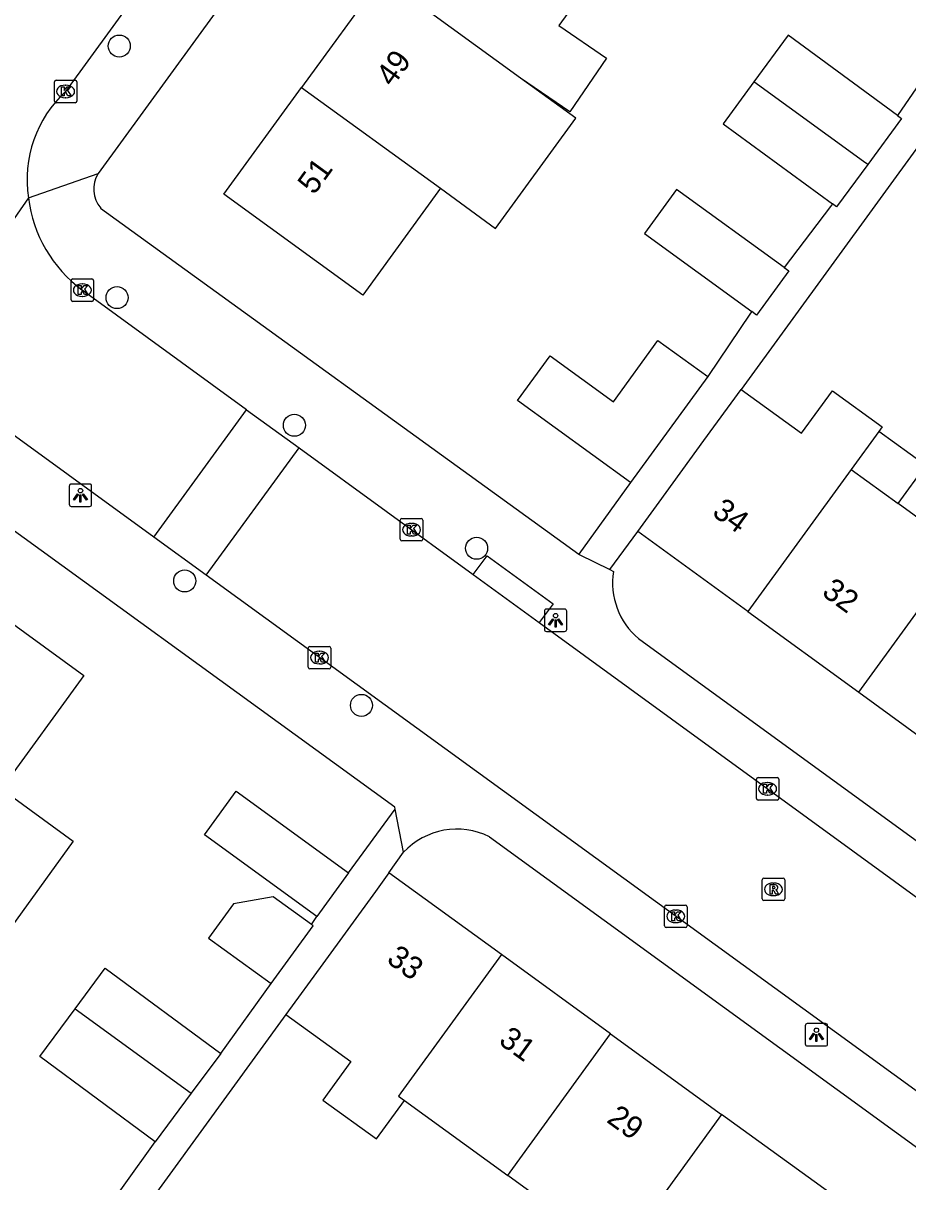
# Model space of a CAD drawing. Extents: x 159675 to 160530, y 382179 to 382901.
# Drawn here: x 160100.6 to 160139.9, y 382538.5 to 382590 of the extents above; entities that cross this region are included whole.
import ezdxf

# ---------------------------------------------------------------- set-up
doc = ezdxf.new("R2010")
doc.units = 0
for name, color, linetype in [('IMGEO_Boom', 7, 'Continuous'), ('IMGEO_Kolk', 7, 'Continuous'), ('IMGEO_Lichtpunt', 7, 'Continuous'), ('IMGEO_Pand', 7, 'Continuous'), ('IMGEO_Pand_nummerreeks', 7, 'Continuous'), ('IMGEO_Rijbaan_lokaal_open', 7, 'Continuous'), ('IMGEO_Rioolput', 7, 'Continuous'), ('IMGEO_Voetpad_open', 7, 'Continuous')]:
    doc.layers.add(name, color=color, linetype=linetype)

msp = doc.modelspace()

# ---------------------------------------------------------------- linework, layer by layer
at = {"layer": 'IMGEO_Boom'}
for centre in [(160104.827, 382589.008), (160104.727, 382577.823), (160112.605, 382572.152), (160120.699, 382566.683), (160107.733, 382565.233), (160115.586, 382559.701)]:
    msp.add_circle(centre, 0.489, dxfattribs=at)
at = {"layer": 'IMGEO_Kolk'}
for p, q in [((160101.942, 382586.562), (160101.942, 382587.414)), ((160102.017, 382587.488), (160102.869, 382587.488)), ((160102.43, 382587.268), (160102.455, 382587.268)), ((160102.943, 382587.414), (160102.943, 382586.562)), ((160102.453, 382586.708), (160102.428, 382586.708)), ((160102.869, 382586.488), (160102.017, 382586.488)), ((160102.686, 382577.731), (160102.686, 382578.583)), ((160102.761, 382578.657), (160103.613, 382578.657)), ((160103.174, 382578.437), (160103.199, 382578.437)), ((160103.687, 382578.583), (160103.687, 382577.731)), ((160103.197, 382577.877), (160103.172, 382577.877)), ((160103.613, 382577.657), (160102.761, 382577.657)), ((160117.386, 382568.009), (160118.238, 382568.009)), ((160117.311, 382567.083), (160117.311, 382567.935)), ((160117.799, 382567.789), (160117.824, 382567.789)), ((160118.312, 382567.935), (160118.312, 382567.083)), ((160118.238, 382567.009), (160117.386, 382567.009)), ((160117.822, 382567.229), (160117.797, 382567.229)), ((160113.298, 382562.324), (160114.15, 382562.324)), ((160113.223, 382561.398), (160113.223, 382562.25)), ((160113.711, 382562.104), (160113.736, 382562.104)), ((160114.224, 382562.25), (160114.224, 382561.398)), ((160114.15, 382561.324), (160113.298, 382561.324)), ((160113.734, 382561.544), (160113.709, 382561.544)), ((160133.129, 382555.567), (160133.129, 382556.419)), ((160133.204, 382556.493), (160134.056, 382556.493)), ((160133.617, 382556.273), (160133.642, 382556.273)), ((160134.13, 382556.419), (160134.13, 382555.567)), ((160133.64, 382555.713), (160133.615, 382555.713)), ((160134.056, 382555.493), (160133.204, 382555.493)), ((160129.048, 382549.897), (160129.048, 382550.749)), ((160129.123, 382550.823), (160129.975, 382550.823)), ((160129.536, 382550.603), (160129.561, 382550.603)), ((160130.049, 382550.749), (160130.049, 382549.897)), ((160129.559, 382550.043), (160129.534, 382550.043)), ((160129.975, 382549.823), (160129.123, 382549.823))]:
    msp.add_line(p, q, dxfattribs=at)
for points in [[(160101.942, 382586.562), (160101.942, 382587.414)], [(160102.017, 382587.488), (160102.869, 382587.488)], [(160102.263, 382587.188), (160102.386, 382587.188), (160102.386, 382587.037), (160102.516, 382587.188), (160102.68, 382587.188), (160102.534, 382587.037), (160102.687, 382586.788), (160102.535, 382586.788), (160102.45, 382586.952), (160102.386, 382586.885), (160102.386, 382586.788), (160102.263, 382586.788), (160102.263, 382587.188)], [(160102.943, 382587.414), (160102.943, 382586.562)], [(160102.869, 382586.488), (160102.017, 382586.488)], [(160102.686, 382577.731), (160102.686, 382578.583)], [(160102.761, 382578.657), (160103.613, 382578.657)], [(160103.007, 382578.357), (160103.13, 382578.357), (160103.13, 382578.206), (160103.26, 382578.357), (160103.424, 382578.357), (160103.278, 382578.206), (160103.431, 382577.957), (160103.279, 382577.957), (160103.194, 382578.121), (160103.13, 382578.054), (160103.13, 382577.957), (160103.007, 382577.957), (160103.007, 382578.357)], [(160103.687, 382578.583), (160103.687, 382577.731)], [(160103.613, 382577.657), (160102.761, 382577.657)], [(160117.386, 382568.009), (160118.238, 382568.009)], [(160117.311, 382567.083), (160117.311, 382567.935)], [(160117.632, 382567.709), (160117.755, 382567.709), (160117.755, 382567.558), (160117.885, 382567.709), (160118.049, 382567.709), (160117.903, 382567.558), (160118.056, 382567.309), (160117.904, 382567.309), (160117.819, 382567.473), (160117.755, 382567.406), (160117.755, 382567.309), (160117.632, 382567.309), (160117.632, 382567.709)], [(160118.312, 382567.935), (160118.312, 382567.083)], [(160118.238, 382567.009), (160117.386, 382567.009)], [(160113.298, 382562.324), (160114.15, 382562.324)], [(160113.223, 382561.398), (160113.223, 382562.25)], [(160113.544, 382562.024), (160113.667, 382562.024), (160113.667, 382561.873), (160113.797, 382562.024), (160113.961, 382562.024), (160113.815, 382561.873), (160113.968, 382561.624), (160113.816, 382561.624), (160113.731, 382561.788), (160113.667, 382561.721), (160113.667, 382561.624), (160113.544, 382561.624), (160113.544, 382562.024)], [(160114.224, 382562.25), (160114.224, 382561.398)], [(160114.15, 382561.324), (160113.298, 382561.324)], [(160133.129, 382555.567), (160133.129, 382556.419)], [(160133.204, 382556.493), (160134.056, 382556.493)], [(160133.45, 382556.193), (160133.573, 382556.193), (160133.573, 382556.042), (160133.703, 382556.193), (160133.867, 382556.193), (160133.721, 382556.042), (160133.874, 382555.793), (160133.722, 382555.793), (160133.637, 382555.957), (160133.573, 382555.89), (160133.573, 382555.793), (160133.45, 382555.793), (160133.45, 382556.193)], [(160134.13, 382556.419), (160134.13, 382555.567)], [(160134.056, 382555.493), (160133.204, 382555.493)], [(160129.048, 382549.897), (160129.048, 382550.749)], [(160129.123, 382550.823), (160129.975, 382550.823)], [(160129.369, 382550.523), (160129.492, 382550.523), (160129.492, 382550.372), (160129.622, 382550.523), (160129.786, 382550.523), (160129.64, 382550.372), (160129.793, 382550.123), (160129.641, 382550.123), (160129.556, 382550.287), (160129.492, 382550.22), (160129.492, 382550.123), (160129.369, 382550.123), (160129.369, 382550.523)], [(160130.049, 382550.749), (160130.049, 382549.897)], [(160129.975, 382549.823), (160129.123, 382549.823)]]:
    msp.add_lwpolyline(points, dxfattribs=at)
for centre, start, end in [((160102.019, 382587.412), 91.552, 178.448), ((160102.019, 382587.412), 91.552, 178.448), ((160102.867, 382587.412), 1.552, 88.448), ((160102.867, 382587.412), 1.552, 88.448), ((160102.019, 382586.564), 181.552, 268.448), ((160102.019, 382586.564), 181.552, 268.448), ((160102.867, 382586.564), 271.552, 358.448), ((160102.867, 382586.564), 271.552, 358.448), ((160102.763, 382578.581), 91.552, 178.448), ((160102.763, 382578.581), 91.552, 178.448), ((160103.611, 382578.581), 1.552, 88.448), ((160103.611, 382578.581), 1.552, 88.448), ((160102.763, 382577.733), 181.552, 268.448), ((160102.763, 382577.733), 181.552, 268.448), ((160103.611, 382577.733), 271.552, 358.448), ((160103.611, 382577.733), 271.552, 358.448), ((160117.388, 382567.933), 91.552, 178.448), ((160117.388, 382567.933), 91.552, 178.448), ((160118.236, 382567.933), 1.552, 88.448), ((160118.236, 382567.933), 1.552, 88.448), ((160117.388, 382567.085), 181.552, 268.448), ((160117.388, 382567.085), 181.552, 268.448), ((160118.236, 382567.085), 271.552, 358.448), ((160118.236, 382567.085), 271.552, 358.448), ((160113.3, 382562.248), 91.552, 178.448), ((160113.3, 382562.248), 91.552, 178.448), ((160114.148, 382562.248), 1.552, 88.448), ((160114.148, 382562.248), 1.552, 88.448), ((160113.3, 382561.4), 181.552, 268.448), ((160113.3, 382561.4), 181.552, 268.448), ((160114.148, 382561.4), 271.552, 358.448), ((160114.148, 382561.4), 271.552, 358.448), ((160133.206, 382556.417), 91.552, 178.448), ((160133.206, 382556.417), 91.552, 178.448), ((160134.054, 382556.417), 1.552, 88.448), ((160134.054, 382556.417), 1.552, 88.448), ((160133.206, 382555.569), 181.552, 268.448), ((160133.206, 382555.569), 181.552, 268.448), ((160134.054, 382555.569), 271.552, 358.448), ((160134.054, 382555.569), 271.552, 358.448), ((160129.125, 382550.747), 91.552, 178.448), ((160129.125, 382550.747), 91.552, 178.448), ((160129.973, 382550.747), 1.552, 88.448), ((160129.973, 382550.747), 1.552, 88.448), ((160129.125, 382549.899), 181.552, 268.448), ((160129.125, 382549.899), 181.552, 268.448), ((160129.973, 382549.899), 271.552, 358.448), ((160129.973, 382549.899), 271.552, 358.448)]:
    msp.add_arc(centre, 0.0765, start, end, dxfattribs=at)
for centre, major_axis, ratio, start_param, end_param in [((160102.429, 382586.988), (-0.387, 0.002), 0.722429, 4.712389, 7.853982), ((160102.454, 382586.988), (-0.39, 0.002), 0.717154, 1.570796, 4.712389), ((160103.173, 382578.157), (-0.387, 0.002), 0.722429, 4.712389, 7.853982), ((160103.198, 382578.157), (-0.39, 0.002), 0.717154, 1.570796, 4.712389), ((160117.798, 382567.509), (-0.387, 0.002), 0.722429, 4.712389, 7.853982), ((160117.823, 382567.509), (-0.39, 0.002), 0.717154, 1.570796, 4.712389), ((160113.71, 382561.824), (-0.387, 0.002), 0.722429, 4.712389, 7.853982), ((160113.735, 382561.824), (-0.39, 0.002), 0.717154, 1.570796, 4.712389), ((160133.616, 382555.993), (-0.387, 0.002), 0.722429, 4.712389, 7.853982), ((160133.641, 382555.993), (-0.39, 0.002), 0.717154, 1.570796, 4.712389), ((160129.535, 382550.323), (-0.387, 0.002), 0.722429, 4.712389, 7.853982), ((160129.56, 382550.323), (-0.39, 0.002), 0.717154, 1.570796, 4.712389)]:
    msp.add_ellipse(centre, major_axis=major_axis, ratio=ratio, start_param=start_param, end_param=end_param, dxfattribs=at)
at = {"layer": 'IMGEO_Lichtpunt'}
for p, q in [((160103.505, 382569.539), (160102.697, 382569.539)), ((160103.505, 382569.539), (160102.697, 382569.539)), ((160102.603, 382569.444), (160102.603, 382568.637)), ((160102.603, 382569.444), (160102.603, 382568.637)), ((160103.599, 382568.637), (160103.599, 382569.444)), ((160103.599, 382568.637), (160103.599, 382569.444)), ((160102.697, 382568.543), (160103.505, 382568.543)), ((160102.697, 382568.543), (160103.505, 382568.543)), ((160123.711, 382563.887), (160123.711, 382563.08)), ((160123.711, 382563.887), (160123.711, 382563.08)), ((160124.613, 382563.982), (160123.805, 382563.982)), ((160124.613, 382563.982), (160123.805, 382563.982)), ((160124.707, 382563.08), (160124.707, 382563.887)), ((160124.707, 382563.08), (160124.707, 382563.887)), ((160123.805, 382562.986), (160124.613, 382562.986)), ((160123.805, 382562.986), (160124.613, 382562.986)), ((160135.299, 382545.462), (160135.299, 382544.655)), ((160135.299, 382545.462), (160135.299, 382544.655)), ((160136.201, 382545.557), (160135.393, 382545.557)), ((160136.201, 382545.557), (160135.393, 382545.557)), ((160136.295, 382544.655), (160136.295, 382545.462)), ((160136.295, 382544.655), (160136.295, 382545.462)), ((160135.393, 382544.561), (160136.201, 382544.561)), ((160135.393, 382544.561), (160136.201, 382544.561))]:
    msp.add_line(p, q, dxfattribs=at)
for points in [[(160102.977, 382569.108), (160103.016, 382569.08), (160102.828, 382568.818), (160102.79, 382568.845), (160102.977, 382569.108)], [(160103.079, 382569.06), (160103.126, 382569.06), (160103.126, 382568.738), (160103.079, 382568.738), (160103.079, 382569.06)], [(160103.189, 382569.08), (160103.227, 382569.107), (160103.414, 382568.845), (160103.375, 382568.817), (160103.189, 382569.08)], [(160124.085, 382563.551), (160124.124, 382563.523), (160123.936, 382563.261), (160123.898, 382563.288), (160124.085, 382563.551)], [(160124.187, 382563.503), (160124.234, 382563.503), (160124.234, 382563.181), (160124.187, 382563.181), (160124.187, 382563.503)], [(160124.297, 382563.523), (160124.335, 382563.55), (160124.522, 382563.288), (160124.483, 382563.26), (160124.297, 382563.523)], [(160135.673, 382545.126), (160135.712, 382545.098), (160135.524, 382544.836), (160135.486, 382544.863), (160135.673, 382545.126)], [(160135.775, 382545.078), (160135.822, 382545.078), (160135.822, 382544.756), (160135.775, 382544.756), (160135.775, 382545.078)], [(160135.885, 382545.098), (160135.923, 382545.125), (160136.11, 382544.863), (160136.071, 382544.835), (160135.885, 382545.098)]]:
    msp.add_lwpolyline(points, dxfattribs=at)
for centre in [(160103.102, 382569.242), (160124.21, 382563.685), (160135.798, 382545.26)]:
    msp.add_circle(centre, 0.0994, dxfattribs=at)
for centre, start, end in [((160102.697, 382569.444), 90, 180), ((160102.697, 382569.444), 90, 180), ((160103.505, 382569.444), 0, 90), ((160103.505, 382569.444), 0, 90), ((160102.697, 382568.637), 180, 270), ((160102.697, 382568.637), 180, 270), ((160103.505, 382568.637), 270, 0), ((160103.505, 382568.637), 270, 360), ((160123.805, 382563.887), 90, 180), ((160123.805, 382563.887), 90, 180), ((160124.613, 382563.887), 0, 90), ((160124.613, 382563.887), 0, 90), ((160123.805, 382563.08), 180, 270), ((160123.805, 382563.08), 180, 270), ((160124.613, 382563.08), 270, 0), ((160124.613, 382563.08), 270, 360), ((160135.393, 382545.462), 90, 180), ((160135.393, 382545.462), 90, 180), ((160136.201, 382545.462), 0, 90), ((160136.201, 382545.462), 0, 90), ((160135.393, 382544.655), 180, 270), ((160135.393, 382544.655), 180, 270), ((160136.201, 382544.655), 270, 0), ((160136.201, 382544.655), 270, 360)]:
    msp.add_arc(centre, 0.0946, start, end, dxfattribs=at)
at = {"layer": 'IMGEO_Pand'}
for points in [[(160126.162, 382592.404), (160124.357, 382589.921), (160126.478, 382588.471), (160124.848, 382586.086), (160122.658, 382587.583)], [(160116.488, 382592.067), (160112.925, 382587.167)], [(160122.658, 382587.583), (160116.488, 382592.067)], [(160139.394, 382585.922), (160134.54, 382589.484), (160133.023, 382587.416)], [(160119.095, 382582.683), (160121.543, 382580.904), (160125.105, 382585.804), (160122.658, 382587.583)], [(160119.095, 382582.683), (160115.643, 382577.934), (160109.474, 382582.419), (160112.925, 382587.167)], [(160112.925, 382587.167), (160119.095, 382582.683)], [(160133.023, 382587.416), (160131.654, 382585.551), (160136.508, 382581.989)], [(160138.076, 382583.742), (160137.892, 382583.876), (160133.023, 382587.416)], [(160139.394, 382585.922), (160139.577, 382585.788), (160138.076, 382583.742)], [(160138.076, 382583.742), (160136.691, 382581.855), (160136.508, 382581.989)], [(160134.369, 382579.161), (160129.589, 382582.637), (160128.16, 382580.671), (160132.921, 382577.209)], [(160134.369, 382579.161), (160134.569, 382579.016), (160133.139, 382577.05), (160132.921, 382577.209)], [(160127.536, 382569.602), (160122.525, 382573.245), (160123.972, 382575.235), (160126.776, 382573.196), (160128.759, 382575.925), (160130.967, 382574.32)], [(160130.967, 382574.32), (160127.536, 382569.602)], [(160127.858, 382567.433), (160128.805, 382568.733), (160130.801, 382571.476), (160132.454, 382573.746)], [(160132.454, 382573.746), (160135.133, 382571.795), (160136.511, 382573.688), (160138.718, 382572.08), (160138.571, 382571.877)], [(160138.571, 382571.877), (160137.341, 382570.188)], [(160139.431, 382568.666), (160140.661, 382570.356), (160138.571, 382571.877)], [(160137.341, 382570.188), (160132.745, 382563.875)], [(160137.341, 382570.188), (160139.431, 382568.666)], [(160142.277, 382566.594), (160139.431, 382568.666)], [(160132.745, 382563.875), (160127.858, 382567.433)], [(160137.679, 382560.282), (160142.277, 382566.594)], [(160093.458, 382560.448), (160097.119, 382565.484), (160103.251, 382561.027), (160099.59, 382555.99)], [(160132.745, 382563.875), (160137.679, 382560.282)], [(160137.679, 382560.282), (160142.488, 382556.781)], [(160099.59, 382555.99), (160102.783, 382553.66), (160099.269, 382548.826), (160096.071, 382551.151)], [(160113.608, 382550.312), (160108.612, 382553.944), (160110.021, 382555.881), (160115.017, 382552.25)], [(160116.806, 382552.256), (160116.205, 382551.429), (160113.867, 382548.212), (160112.233, 382545.963)], [(160115.017, 382552.25), (160113.608, 382550.312)], [(160121.807, 382548.622), (160116.806, 382552.256)], [(160113.36, 382549.958), (160111.668, 382551.187), (160109.901, 382550.874), (160108.798, 382549.356), (160111.578, 382547.337)], [(160111.578, 382547.337), (160113.44, 382549.9), (160113.36, 382549.958)], [(160121.807, 382548.622), (160117.342, 382542.478), (160117.233, 382542.33), (160117.494, 382542.141)], [(160126.656, 382545.098), (160121.807, 382548.622)], [(160102.861, 382546.215), (160104.194, 382548.012), (160109.338, 382544.231)], [(160106.42, 382540.296), (160101.292, 382544.099), (160102.861, 382546.215)], [(160102.861, 382546.215), (160108.025, 382542.461)], [(160112.233, 382545.963), (160115.121, 382543.865), (160113.876, 382542.15), (160116.248, 382540.426), (160117.494, 382542.141)], [(160122.082, 382538.806), (160122.19, 382538.954), (160126.656, 382545.098)], [(160126.656, 382545.098), (160131.584, 382541.517)], [(160109.338, 382544.231), (160108.025, 382542.461)], [(160108.025, 382542.461), (160106.42, 382540.296)], [(160117.494, 382542.141), (160122.082, 382538.806)], [(160131.584, 382541.517), (160127.119, 382535.372), (160127.01, 382535.224)], [(160136.387, 382538.026), (160131.584, 382541.517)], [(160127.01, 382535.224), (160122.082, 382538.806)]]:
    msp.add_lwpolyline(points, dxfattribs=at)
at = {"layer": 'IMGEO_Rijbaan_lokaal_open'}
for points in [[(160127.333, 382621.232), (160126.918, 382620.636), (160102.443, 382586.988)], [(160100.791, 382582.263), (160094.604, 382573.357)], [(160110.485, 382572.841), (160103.182, 382578.158)], [(160106.361, 382567.175), (160098.735, 382572.717)], [(160106.361, 382567.175), (160110.485, 382572.841)], [(160110.485, 382572.841), (160112.814, 382571.146)], [(160108.691, 382565.482), (160112.814, 382571.146)], [(160112.814, 382571.146), (160120.554, 382565.511)], [(160108.691, 382565.482), (160106.361, 382567.175)], [(160164.514, 382524.914), (160108.691, 382565.482)], [(160120.554, 382565.511), (160123.485, 382563.377)], [(160123.485, 382563.377), (160153.206, 382541.739), (160168.596, 382530.532)]]:
    msp.add_lwpolyline(points, dxfattribs=at)
for centre, radius, start, end in [((160106.087, 382583.063), 5.356, 132.8715, 188.5863), ((160106.788, 382583.007), 6.043, 187.0728, 233.3654)]:
    msp.add_arc(centre, radius, start, end, dxfattribs=at)
at = {"layer": 'IMGEO_Rioolput'}
for p, q in [((160133.462, 382552.023), (160134.314, 382552.023)), ((160133.387, 382551.097), (160133.387, 382551.949)), ((160133.875, 382551.803), (160133.9, 382551.803)), ((160134.388, 382551.949), (160134.388, 382551.097)), ((160134.314, 382551.023), (160133.462, 382551.023)), ((160133.898, 382551.243), (160133.873, 382551.243))]:
    msp.add_line(p, q, dxfattribs=at)
for points in [[(160133.462, 382552.023), (160134.314, 382552.023)], [(160133.387, 382551.097), (160133.387, 382551.949)], [(160133.976, 382551.721), (160133.724, 382551.723), (160133.724, 382551.323)], [(160133.724, 382551.323), (160133.848, 382551.323), (160133.848, 382551.485), (160133.859, 382551.485)], [(160133.902, 382551.642), (160133.848, 382551.642), (160133.848, 382551.561)], [(160133.848, 382551.561), (160133.9, 382551.561)], [(160134.388, 382551.949), (160134.388, 382551.097)], [(160134.314, 382551.023), (160133.462, 382551.023)], [(160133.906, 382551.456), (160133.977, 382551.323), (160134.117, 382551.323), (160134.052, 382551.449)]]:
    msp.add_lwpolyline(points, dxfattribs=at)
for centre, radius, start, end in [((160133.464, 382551.947), 0.0765, 91.552, 178.448), ((160133.464, 382551.947), 0.0765, 91.552, 178.448), ((160134.312, 382551.947), 0.0765, 1.552, 88.448), ((160134.312, 382551.947), 0.0765, 1.552, 88.448), ((160133.858, 382551.432), 0.0533, 26.0293, 88.6989), ((160133.884, 382551.75), 0.19, 274.7715, 282.9687), ((160133.908, 382551.546), 0.0964, 77.0061, 93.1865), ((160133.922, 382551.603), 0.0378, 276.6634, 79.6772), ((160133.975, 382551.611), 0.109, 350.3612, 89.416), ((160133.973, 382551.611), 0.112, 277.5842, 350.9817), ((160133.957, 382551.396), 0.108, 29.5134, 73.7905), ((160133.464, 382551.099), 0.0765, 181.552, 268.448), ((160133.464, 382551.099), 0.0765, 181.552, 268.448), ((160134.312, 382551.099), 0.0765, 271.552, 358.448), ((160134.312, 382551.099), 0.0765, 271.552, 358.448)]:
    msp.add_arc(centre, radius, start, end, dxfattribs=at)
for centre, major_axis, ratio, start_param, end_param in [((160133.874, 382551.523), (-0.387, 0.002), 0.722429, 4.712389, 7.853982), ((160133.899, 382551.523), (-0.39, 0.002), 0.717154, 1.570796, 4.712389)]:
    msp.add_ellipse(centre, major_axis=major_axis, ratio=ratio, start_param=start_param, end_param=end_param, dxfattribs=at)
at = {"layer": 'IMGEO_Voetpad_open'}
for points in [[(160131.588, 382621.403), (160103.888, 382583.337)], [(160143.351, 382591.675), (160143.206, 382591.48), (160139.394, 382585.922)], [(160143.635, 382582.495), (160140.567, 382584.89), (160132.454, 382573.746)], [(160100.791, 382582.263), (160103.888, 382583.337)], [(160136.508, 382581.989), (160136.426, 382581.878), (160134.369, 382579.161)], [(160104, 382581.805), (160125.236, 382566.426)], [(160132.921, 382577.209), (160132.865, 382577.134), (160130.967, 382574.32)], [(160117.084, 382555.093), (160117.069, 382555.171), (160096.153, 382570.347)], [(160127.536, 382569.602), (160125.236, 382566.426)], [(160126.619, 382565.733), (160127.858, 382567.433)], [(160125.236, 382566.426), (160125.255, 382566.413), (160126.619, 382565.733)], [(160120.554, 382565.511), (160121.166, 382566.352), (160124.097, 382564.218), (160123.485, 382563.377)], [(160126.619, 382565.733), (160126.781, 382565.652)], [(160127.897, 382562.669), (160184.209, 382521.695), (160184.808, 382522.535)], [(160115.017, 382552.25), (160117.084, 382555.093)], [(160117.459, 382553.168), (160117.084, 382555.093)], [(160121.273, 382553.859), (160177.794, 382512.755), (160177.234, 382512.001)], [(160116.806, 382552.256), (160117.459, 382553.168)], [(160113.36, 382549.958), (160113.608, 382550.312)], [(160109.338, 382544.231), (160111.578, 382547.337)], [(160112.233, 382545.963), (160104.558, 382535.4), (160107.404, 382533.311), (160109.54, 382531.743), (160111.516, 382530.293), (160117.181, 382526.205), (160119.318, 382524.636), (160121.293, 382523.187), (160126.833, 382519.19), (160128.969, 382517.622), (160130.945, 382516.172), (160130.979, 382516.218), (160136.587, 382512.101), (160138.724, 382510.532), (160140.699, 382509.083), (160146.468, 382504.92)], [(160102.285, 382534.528), (160106.42, 382540.296)]]:
    msp.add_lwpolyline(points, dxfattribs=at)
for centre, radius, start, end in [((160104.993, 382582.648), 1.302, 148.0337, 220.3289), ((160129.981, 382565.149), 3.239, 171.0643, 229.9594), ((160119.828, 382550.965), 3.235, 63.4619, 137.0764)]:
    msp.add_arc(centre, radius, start, end, dxfattribs=at)

# ---------------------------------------------------------------- texts
at = {"layer": 'IMGEO_Pand_nummerreeks'}
for s, rotation, p in [('49', 53.9841, (160116.965, 382587.147)), ('51', 53.9854, (160113.483, 382582.354)), ('34', 323.938, (160131.113, 382568.18)), ('32', 323.938, (160135.99, 382564.628)), ('33', 323.9953, (160116.653, 382548.312)), ('31', 323.9953, (160121.633, 382544.693)), ('29', 323.9944, (160126.431, 382541.207))]:
    msp.add_text(s, height=1, rotation=rotation, dxfattribs=at).set_placement(p)

doc.saveas('drawing.dxf')
